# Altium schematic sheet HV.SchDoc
size A2; SheetNumber: 3; SheetTotal: 3
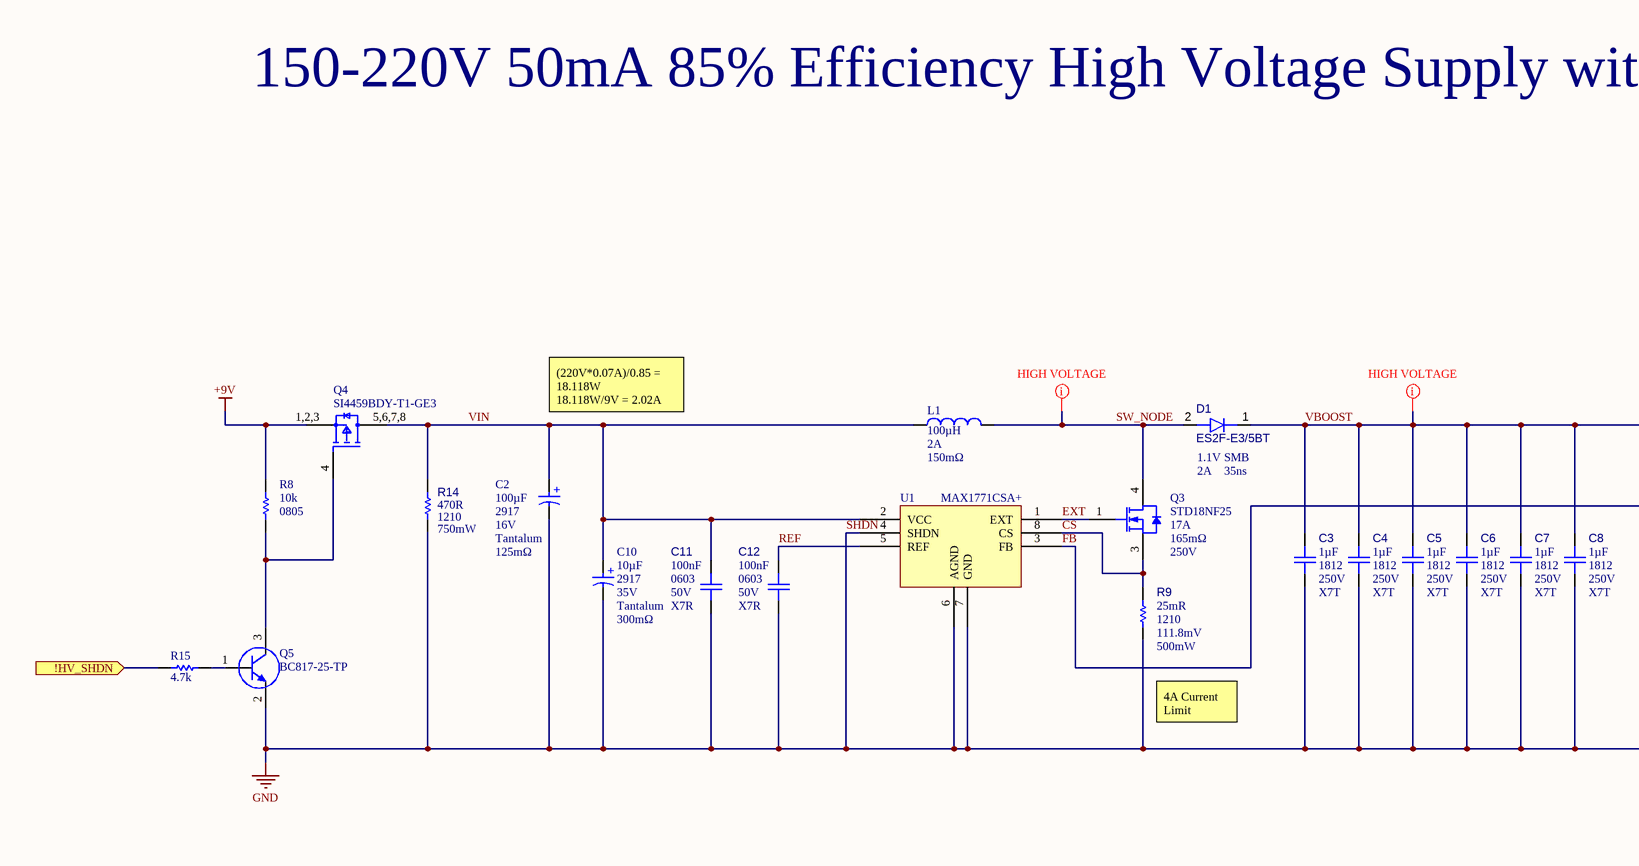
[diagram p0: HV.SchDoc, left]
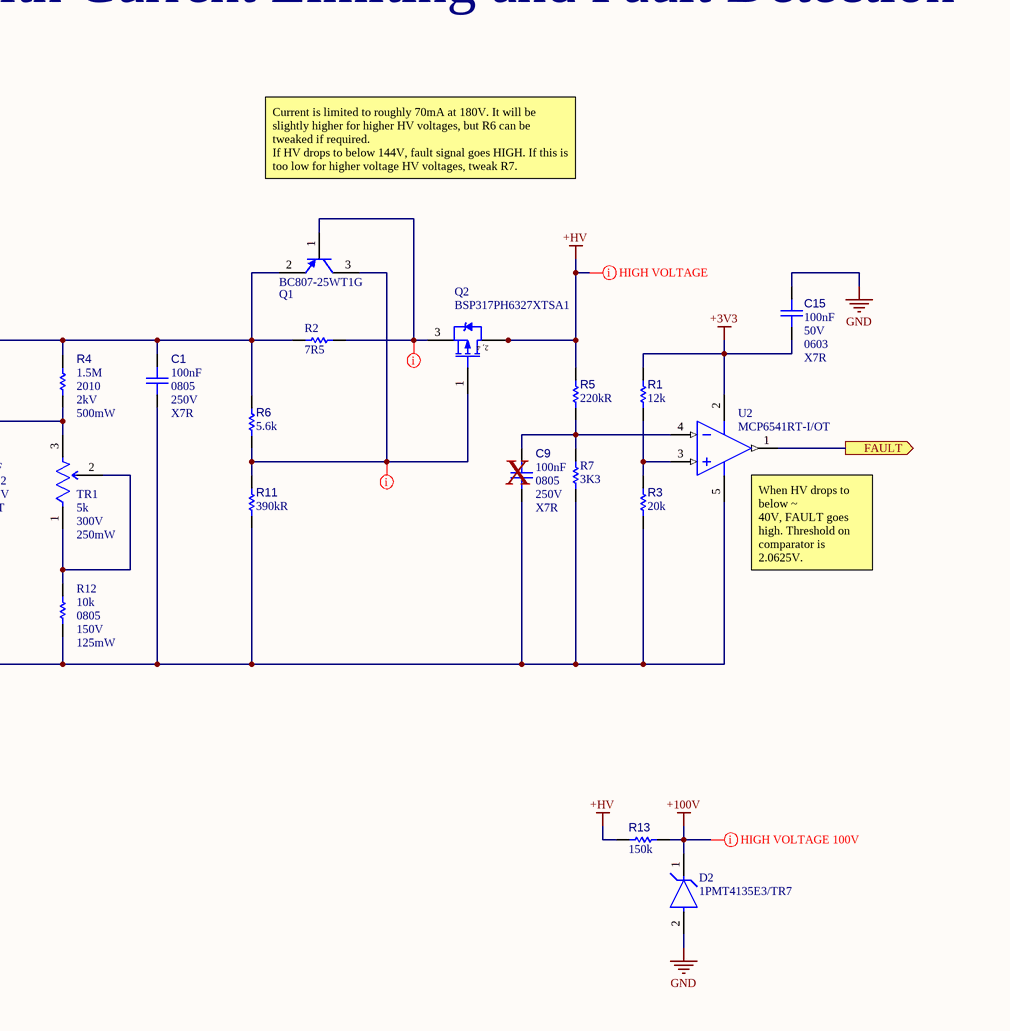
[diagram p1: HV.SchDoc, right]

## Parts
?  (no value)
C1  value 100nF  Voltage Rating: 250V  Dielectric: X7R  Case/Package: 0805  [CAPC2013X95X50NL10T25-Wider-Spacing]  (hidden comment: CC0805KKX7RYBB104)
C2  value 100µF  Case/Package: 2917  Dielectric Material: Tantalum  ESR (Equivalent Series Resistance): 125mΩ  Voltage: 16V  [CAPMP7344X31N]  (hidden comment: TPSD107M016R0125)
C3  value 1µF  Dielectric: X7T  Case Code (Imperial): 1812  Voltage Rating (DC): 250V  [CAPC4532X28N]  (hidden comment: CGA8P3X7T2E105K250KA)
C4  value 1µF  Dielectric: X7T  Case Code (Imperial): 1812  Voltage Rating (DC): 250V  [CAPC4532X28N]  (hidden comment: CGA8P3X7T2E105K250KA)
C5  value 1µF  Dielectric: X7T  Case Code (Imperial): 1812  Voltage Rating (DC): 250V  [CAPC4532X28N]  (hidden comment: CGA8P3X7T2E105K250KA)
C6  value 1µF  Dielectric: X7T  Case Code (Imperial): 1812  Voltage Rating (DC): 250V  [CAPC4532X28N]  (hidden comment: CGA8P3X7T2E105K250KA)
C7  value 1µF  Dielectric: X7T  Case Code (Imperial): 1812  Voltage Rating (DC): 250V  [CAPC4532X28N]  (hidden comment: CGA8P3X7T2E105K250KA)
C8  value 1µF  Dielectric: X7T  Case Code (Imperial): 1812  Voltage Rating (DC): 250V  [CAPC4532X28N]  (hidden comment: CGA8P3X7T2E105K250KA)
C9  value 100nF  Voltage Rating: 250V  Dielectric: X7R  Case/Package: 0805  [CAPC2013X95X50NL10T25]  (hidden comment: CC0805KKX7RYBB104)
C10  value 10µF  Voltage Rating: 35V  Case/Package: 2917  Capacitor Type: Tantalum  ESR (Equivalent Series Resistance): 300mΩ  [CAPMP7344X31N]  (hidden comment: TPSD106K035R0300)
C11  value 100nF  Voltage Rating: 50V  Case/Package: 0603  Dielectric: X7R  [CAPC1608X09N]  (hidden comment: CGA3E2X7R1H104K080AA)
C12  value 100nF  Voltage Rating: 50V  Case/Package: 0603  Dielectric: X7R  [CAPC1608X09N]  (hidden comment: CGA3E2X7R1H104K080AA)
C15  value 100nF  Voltage Rating: 50V  Case/Package: 0603  Dielectric: X7R  [CAPC1608X09N]  (hidden comment: CGA3E2X7R1H104K080AA)
D1  ES2F-E3/5BT  Recovery Time: 35ns  Max Output current: 2A  Forward Voltage: 1.1V  Case/Package: SMB  [DIOM4336X24N]
D2  1PMT4135E3/TR7  [FP-DO-216-MFG]
L1  value 100µH  DC Resistance (DCR): 150mΩ  Saturation Current: 2A  [BOUR-SRR1280-2_V]  (hidden comment: SRR1280-101M)
Q1  BC807-25WT1G  [ONSC-SC-70-3-419-04_V]
Q2  BSP317PH6327XTSA1  [INF-PG-SOT223_SC-73_N]
Q3  STD18NF25  Continuous Drain Current (ID): 17A  Rds On Max: 165mΩ  Drain to Source Voltage (Vdss): 250V  [DPAK229P972X240-3N]
Q4  SI4459BDY-T1-GE3  [SI4459BDY-T1-GE3-Footprint-1]
Q5  BC817-25-TP  [SOT95P237X110-3N]
R1  value 12k  [RESC1609X55X30NL15T15]  (hidden comment: ERJ3EKF1202V)
R2  value 7R5  [RESC1608X55X25NL10T15]  (hidden comment: AC0603FR-077R5L)
R3  value 20k  [RESC1608X55X30NL15T15]  (hidden comment: ERJ3EKF2002V)
R4  value 1.5M  Power Dissipation: 500mW  Working Voltage: 2kV  Case/Package: 2010  [RESC5125X07N]  (hidden comment: CRMA2010AF1M50FKEF)
R5  value 220kR  [RESC5125X07N]  (hidden comment: 5-2176330-3)
R6  value 5.6k  [RESC1609X55X30NL15T15]  (hidden comment: ERJ-3EKF5601V)
R7  value 3K3  [RESC1608X55X25NL10T15]  (hidden comment: ERJ-3RBD3301V)
R8  value 10k  Case/Package: 0805  [RESC2013X50X35NL15T15]  (hidden comment: Resistor 10k +/-1% 0805 125 mW)
R9  value 25mR  Case/Package: 1210  Power Dissipation: 500mW  Working Voltage: 111.8mV  [RESC3126X65X50NL10T20]  (hidden comment: RL1210FR-070R025L)
R11  value 390kR  [RESC5125X07N]  (hidden comment: 5-2176347-6)
R12  value 10k  Power: 125mW  Case/Package: 0805  Voltage Rating: 150V  [RESC2013X50X35NL15T15]  (hidden comment: Resistor 10k +/-1% 0805 125 mW)
R13  value 150k  [RESC3216X06N]  (hidden comment: CRCW1206150KFKEA)
R14  value 470R  Power Dissipation: 750mW  Case Code (Imperial): 1210  [RESC3126X65X50NL10T20]  (hidden comment: CRCW1210470RFKEAHP)
R15  value 4.7k  [RESC1608X55X25NL10T15]  (hidden comment: Resistor 4k7 +/-1% 0603 100 mW)
TR1  value 5k  Voltage Rating: 300V  Power: 250mW  [3266W-1-502LF-Footprint-1]  (hidden comment: 3266W-1-502LF)
U1  MAX1771CSA+  [Copy of ADI-R-8_N]
U2  MCP6541RT-I/OT  [SOT-23-OT5_N]

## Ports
!HV_SHDN (in), FAULT (out)

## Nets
+3V3: C15.1 R1.2 U2.2(VDD)
+9V: Q4.1,2,3(S) R8.2
+100V: D2.1(C) R13.2
+HV: Q2.2(DRAIN) Q2.4(DRAIN) R5.2 R13.1
SHDN: C1.2 C2.2(N) C3.2 C4.2 C5.2 C6.2 C7.2 C8.2 C9.2 C10.2(N) C11.2 C12.2 C15.2 D2.2(A) Q5.2(E) R3.1 R7.1 R9.1 R11.1 R12.1 R14.1 U1.4(SHDN) U1.6(AGND) U1.7(GND) U2.5(VSS)  [also labelled GND]
!HV_SHDN: R15.2 ; port !HV_SHDN
CS: Q3.3(S) R9.2 U1.8(CS)
EXT: Q3.1(G) U1.1(EXT)
FAULT: U2.1(OUT) ; port FAULT
FB: R4.1 TR1.3(CW) U1.3(FB)
REF: C12.1 U1.5(REF)
SW_NODE: D1.2(A) L1.2 Q3.4(D)
VBOOST: C1.1 C3.1 C4.1 C5.1 C6.1 C7.1 C8.1 D1.1(K) Q1.2(E) R2.1 R4.2 R6.2
VIN: C2.1(P) C10.1(P) C11.1 L1.1 Q4.5,6,7,8(D) R14.2 U1.2(VCC)
NetC9_1: C9.1 R5.1 R7.2 U2.4(VIN-)
NetQ1_1: Q1.1(B) Q2.3(SOURCE) R2.2
NetQ1_3: Q1.3(C) Q2.1(GATE) R6.1 R11.2
NetQ4_4: Q4.4(G) Q5.3(C) R8.1
NetQ5_1: Q5.1(B) R15.1
NetR1_1: R1.1 R3.2 U2.3(VIN+)
NetR12_2: R12.2 TR1.1(CCW) TR1.2(WIPER)

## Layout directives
net class HIGH VOLTAGE 100V: +100V
net class HIGH VOLTAGE: +HV, NetQ1_1, NetQ1_3, SW_NODE, VBOOST

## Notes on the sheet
- 150-220V 50mA 85% Efficiency High Voltage Supply with Current Limiting and Fault Detection
- Current is limited to roughly 70mA at 180V. It will be slightly higher for higher HV voltages, but R6 can be tweaked if required.
  If HV drops to below 144V, fault signal goes HIGH. If this is too low for higher voltage HV voltages, tweak R7.
- (220V*0.07A)/0.85 = 18.118W
  18.118W/9V = 2.02A
- (near C9) X
- (near U2) When HV drops to below ~
  40V, FAULT goes high. Threshold on comparator is 2.0625V.
- 4A Current Limit

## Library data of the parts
? = CMP-00003-4: The KETS Schematic Sheet Title Block
C1 C9 = CMP-00390-2: Ceramic Capacitor, Ceramic, 250V, 10% +Tol, 10% -Tol, X7R, 15% TC, 0.1uF, Surface Mount, 0805
C2 = CMP-001-00157-2: Cap Tant Solid 100uF 16V D CASE 20% (7.3 X 4.3 X 2.9mm) SMD 7343-31 0.125 Ohm 125AHA T/R; Ripple Current: 438mA; Capacitor Type: Tantalum Capacitor; Dissipation Factor: 6%; Polarity: Polar; Leakage Current: 16µA
C3-C8 = CMP-001-00159-1: CGA Series 1812 1 uF 250 V ±10 % Tolerance X7T SMT Multilayer Ceramic Capacitor; Manufacturer Lifecycle Status: PRODUCTION; Capacitor Type: MLCC; Tolerance: 10%
C10 = CMP-001-00158-1: Capacitor Tantalum Solid 10uF 35V D CASE 10% (7.3 X 4.3 X 2.9mm) SMD 7343-31 0.3 Ohm 125C T/R; Dissipation Factor: 6%; Leakage Current: 3.5µA; Ripple Current: 283mA; Polarity: Polar; Approvals: IEC
C11 C12 C15 = CMP-001-00101-1: Ceramic Capacitor, Multilayer, Ceramic, 50V, 10% +Tol, 10% -Tol, X7R, 15% TC, 0.1uF, Surface Mount, 0603; Reference Standard: AEC-Q200; Multilayer: Yes
D1 = CMP-004-00061-1: Rectifier Diode, 1 Phase, 1 Element, 2A, 300V V(RRM), Silicon, DO-214AA; Peak Reverse Current: 10µA; Element Configuration: Single; Reverse Recovery Time: 50ns; Max Forward Surge Current (Ifsm): 50A; Number of Elements: 1
D2 = CMP-004-00063-1: Diode Zener Single 100V 5% 1W 2-Pin(1+Tab) Power Mite T/R; Impedance: 250Ω; Max Junction Temperature (Tj): 150°C; Max Reverse Leakage Current: 10nA; Reverse Voltage: 76V; Forward Voltage: 1.1V
L1 = CMP-006-00066-1: Inductor Power Shielded Wirewound 100uH 20% 1KHz 18Q-Factor Ferrite 2.1A 0.15Ohm DCR T/R; Q Factor: 18; Material: Steel; Shielding: Yes; Number of Circuits: 1; Frequency: 4.5MHz
Q1 = CMP-013-00064-1: Small Signal Bipolar Transistor, 0.5A I(C), 45V V(BR)CEO, 1-Element, PNP, Silicon; Manufacturer Lifecycle Status: ACTIVE; Frequency: 100MHz; Collector Base Voltage (VCBO): 50V; Collector Emitter Saturation Voltage: -700mV; Element Configuration: Single; Number of Elements: 1; Max Power Dissipation: 460mW; Max Collector Current: 500mA; Emitter Base Voltage (VEBO): 5V; hFE Min: 160
Q2 = CMP-013-00065-1: MOSFET P-CH 250V 430MA SOT223-4 P-Channel 250 V 430mA (Ta) 1.8W (Ta) Surface Mount PG-SOT223-4; Turn-Off Delay Time: 254ns; Rise Time: 11.1ns; Max Dual Supply Voltage: -250V; Turn-On Delay Time: 5.7ns; Gate to Source Voltage (Vgs): 20V; Rds On Max: 4Ω; Element Configuration: Single; Nominal Vgs: 2V; Fall Time: 67ns; Input Capacitance: 210pF; Number of Elements: 1
Q3 = CMP-013-00061-1: N-Channel 250 V 0.165 Ohm Surface Mount STripFet II Power MosFet - TO-252-3; pin to pad: 2, 4>4; Turn-On Delay Time: 8.8ns; Rise Time: 17.2ns; Power Dissipation: 110W; Number of Elements: 1; Gate to Source Voltage (Vgs): 20V; Turn-Off Delay Time: 21ns; Input Capacitance: 1nF
Q4 = CMP-013-00066-1: Transistor MOSFET P-CH 30V 27.8A 8-Pin SOIC; Drain to Source Resistance: 4.9mΩ; Number of Elements: 1; Max Power Dissipation: 5.6W
Q5 = CMP-013-00044-4: Small Signal Bipolar Transistor, 0.5A I(C), 45V V(BR)CEO, 1-Element, NPN, Silicon; Power: 300mW; Transistor Type: BJT; Frequency: 100MHz
R1 = CMP-009-00230-1: Fixed Resistor, Metal Glaze/thick Film, 0.1W, 12000ohm, 75V, 1% +/-Tol, 100ppm/Cel, Surface Mount, 0603; Package Length: 1.6mm; Power: 100mW; Package Width: 0.8mm; Package Height: 0.45mm; Rated Temperature: 70°C; Reference Standard: AEC-Q200; Temperature Coefficient: 100ppm/°C
R2 = CMP-00401-2: Res Thick Film 0603 7.5 Ohm 1% 0.1W(1/10W) ±200ppm/C Pad SMD T/R Automotive AEC-Q200; Power: 100mW; Voltage Rating: 75V; Temperature Coefficient: 200ppm/°C
R3 = CMP-009-00244-1: Fixed Resistor, Metal Glaze/thick Film, 0.1W, 20000ohm, 75V, 1% +/-Tol, 100ppm/Cel, Surface Mount, 0603; Power: 100mW; Package Width: 0.8mm; Reference Standard: AEC-Q200; Temperature Coefficient: 100ppm/°C; Package Height: 0.45mm; Package Length: 1.6mm; Rated Temperature: 70°C
R4 = CMP-009-00356-2: Fixed Resistor, Metal Glaze/thick Film, 0.5W, 1.5e+06ohm, 2000V, 1% +/-Tol, 100ppm/Cel, Surface Mount, 2010; Temperature Coefficient: 100ppm/°C
R5 = CMP-00408-2: Fixed Resistor, Thick Film, 1.25W, 220000ohm, 400V, 1% +/-Tol, 100ppm/Cel, Surface Mount, 2010; Temperature Coefficient: 100ppm/°C
R6 = CMP-009-00257-2: Fixed Resistor, Metal Glaze/thick Film, 0.1W, 5600ohm, 75V, 1% +/-Tol, 100ppm/Cel, Surface Mount, 0603; Rated Temperature: 70°C; Package Width: 0.8mm; Power: 100mW; Reference Standard: AEC-Q200; Package Length: 1.6mm; Temperature Coefficient: 100ppm/°C; Package Height: 0.45mm
R7 = CMP-00199-2: Fixed Resistor, Metal Glaze/thick Film, 0.1W, 3300ohm, 75V, 0.5% +/-Tol, 50ppm/Cel, Surface Mount, 0603; Power: 100mW; Working Voltage: 50V; Rated Temperature: 70°C
R8 = CMP-009-00018-11: Chip Resistor, 10 KOhm, +/- 1%, 125 mW, -55 to 155 degC, 0805 (2012 Metric); Power: 125mW; Voltage Rating: 150V
R9 = CMP-00400-2: Fixed Resistor, Metal Glaze/thick Film, 0.5W, 0.025ohm, 0.1118V, 1% +/-Tol, 1000ppm/Cel, Surface Mount, 1210; Temperature Coefficient: 1000ppm/°C
R11 = CMP-00393-1: Res Thick Film 2010 390K Ohm 1% 0.75W(3/4W) ±100ppm/C Pad SMD Automotive T/R; Temperature Coefficient: 100ppm/°C; Working Voltage: 200V; Power Dissipation: 750mW
R12 = CMP-009-00018-11: Chip Resistor, 10 KOhm, +/- 1%, 125 mW, -55 to 155 degC, 0805 (2012 Metric)
R13 = CMP-009-00239-1: Fixed Resistor, Metal Glaze/thick Film, 0.25W, 150000ohm, 200V, 1% +/-Tol, 100ppm/Cel, Surface Mount, 1206; Rated Temperature: 70°C; Reference Standard: AEC-Q200; Package Height: 0.55mm; Package Width: 1.6mm; Package Length: 3.2mm; Temperature Coefficient: 100ppm/°C; Power: 250mW; Additional Feature: RATED AC VOLTAGE (V): 200
R14 = CMP-00406-2: Res Thick Film 1210 470 Ohm 1% 0.75W(3/4W) ±100ppm/C Pad SMD Automotive T/R; Working Voltage: 200V; Temperature Coefficient: 100ppm/°C
R15 = CMP-009-00031-13: Chip Resistor, 4.7 KOhm, +/- 1%, 0.1 W, -55 to 155 degC, 0603 (1608 Metric); Power: 100mW
TR1 = CMP-009-00358-1: Cermet trimmer potentiometer, 12 turns, 5 kΩ, 0.25 W, THT, on top, 3266W-1-502LF; Color: Blue; Number of Turns: 12; Lead Diameter: 460µm; Lead Length: 4.88mm; Tolerance: 10%; Pitch: 2.54mm; Temperature Coefficient: 100ppm/°C
U1 = CMP-019-00098-2: DC-DC Switching Boost (Step Up) Regulator, Adjustable, 2 V-16.5 Vin, 2V-12Vout, 2Aout, SOIC-8; Manufacturer Lifecycle Status: PRODUCTION; Evaluation Kit: Yes; Number of Outputs: 1; Frequency: 300kHz; Output Current: 2A; Output Voltage: 2V
U2 = CMP-00399-1: Comparator Single R-R I/O 5.5V 5-Pin SOT-23 T/R Automotive AEC-Q100; Output Type: Push-Pull; Number of Elements: 1; Output Current per Channel: 2mA; Common Mode Rejection Ratio: 70dB; Response Time: 4µs; Max Input Current: 1pA; Max Supply Current: 1mA; Propagation Delay: 8µs; Quiescent Current: 1µA; Min Supply Voltage: 1.6V; Input Offset Voltage (Vos): 7mV; Hysteresis: 6.5mV; Power Supply Rejection Ratio (PSRR): 80dB; Natural Thermal Resistance: 256°C/W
